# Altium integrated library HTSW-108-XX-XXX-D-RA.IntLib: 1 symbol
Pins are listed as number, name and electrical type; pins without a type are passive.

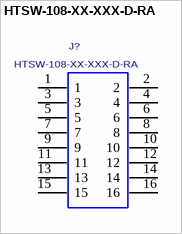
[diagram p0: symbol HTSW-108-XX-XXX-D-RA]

## HTSW-108-XX-XXX-D-RA
designator J?
.025 SQ POST HI-TEMP DOUBLE ROW TERMINAL STRIP ASSEMBLY, 16 PINS.; MANUFACTURER: SAMTEC
footprint HTSW-108-XX-XXX-D-RA
pins: 1, 2, 3, 4, 5, 6, 7, 8, 9, 10, 11, 12, 13, 14, 15, 16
